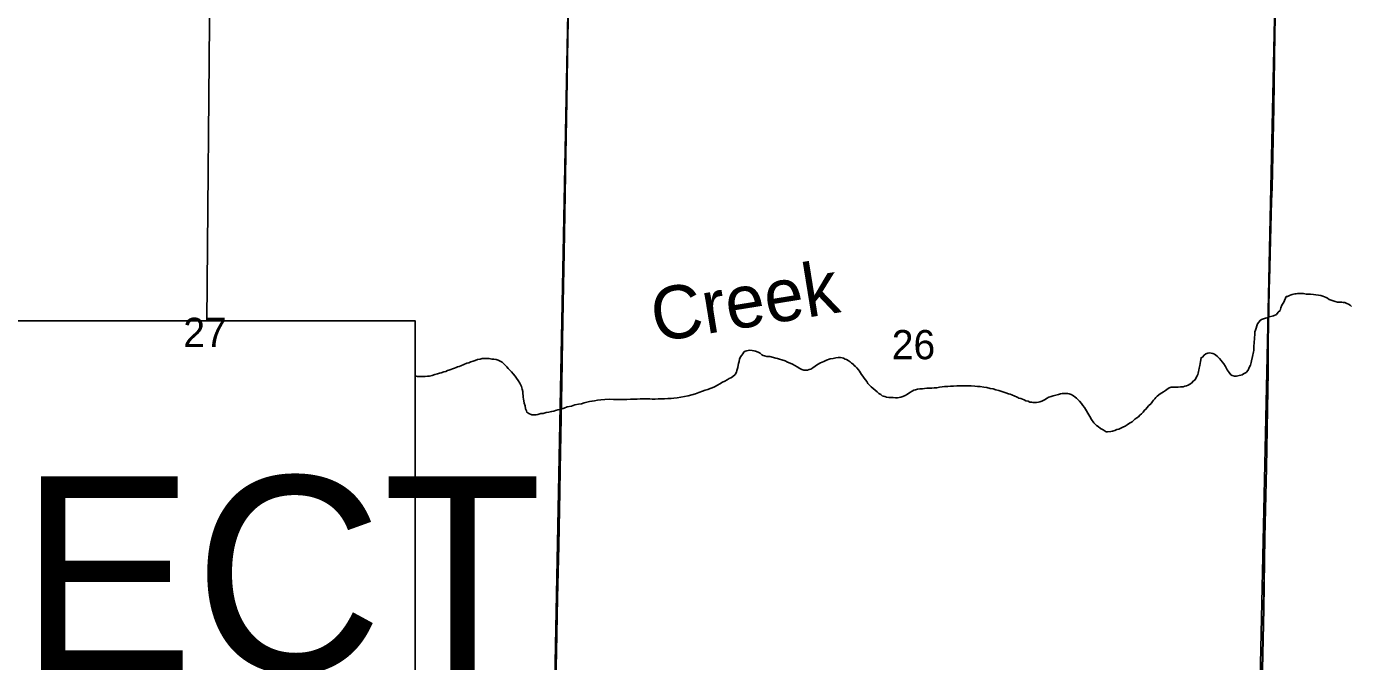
# Model space of a CAD drawing. Extents: x 2.4 to 73.1, y 4.5 to 25.6.
# Drawn here: x 32.094 to 33.042, y 19.109 to 19.564 of the extents above; entities that cross this region are included whole.
import ezdxf

# ---------------------------------------------------------------- set-up
doc = ezdxf.new("R2010")
doc.units = 0
for name, color, linetype in [('GM_X_Minor_Lake_Text', 7, 'Continuous'), ('GM_X_Minor_River', 7, 'Continuous'), ('GM_X_Section', 7, 'Continuous'), ('GM_X_Section_Text', 7, 'Continuous'), ('GM_X_State_Route', 7, 'Continuous'), ('GM_X_Township', 7, 'Continuous'), ('GM_X_Township_Road', 7, 'Continuous'), ('SH_Text', 7, 'Continuous')]:
    doc.layers.add(name, color=color, linetype=linetype)

msp = doc.modelspace()

# ---------------------------------------------------------------- linework, layer by layer
at = {"layer": 'GM_X_Minor_River'}
for points in [[(32.22285, 19.35283), (32.22507, 19.59303), (30.44608, 19.62066)], [(33.04282, 19.36291), (33.04187, 19.36386), (33.04073, 19.36463), (33.03959, 19.3652), (33.03807, 19.36578), (33.03693, 19.36597), (33.03579, 19.36616), (33.03465, 19.36617), (33.0337, 19.36617), (33.03275, 19.36617), (33.03104, 19.36656), (33.02971, 19.36694), (33.02838, 19.36751), (33.02686, 19.36809), (33.02553, 19.36885), (33.02458, 19.36943), (33.02344, 19.37), (33.0223, 19.37038), (33.02078, 19.37096), (33.01565, 19.37154), (33.01356, 19.37174), (33.01204, 19.37193), (33.01033, 19.37194), (33.00842, 19.37232), (33.00691, 19.37233), (33.00576, 19.37233), (33.00424, 19.37234), (33.00329, 19.37215), (33.00234, 19.37215), (33.00044, 19.37159), (32.99949, 19.3714), (32.99853, 19.37083), (32.99701, 19.37027), (32.99606, 19.37008), (32.99434, 19.36609), (32.99301, 19.364), (32.99224, 19.36192), (32.99167, 19.36021), (32.99033, 19.35888), (32.989, 19.35717), (32.98691, 19.35642), (32.98596, 19.35604), (32.98386, 19.35548), (32.98253, 19.35491), (32.9812, 19.35454), (32.97968, 19.35416), (32.97835, 19.35359)], [(32.97835, 19.35359), (32.97739, 19.35303), (32.97644, 19.35189), (32.97549, 19.35056), (32.97396, 19.34601), (32.97357, 19.34487), (32.97357, 19.34316), (32.97337, 19.34031), (32.97318, 19.33708), (32.97298, 19.33461), (32.97279, 19.33157), (32.97259, 19.33043), (32.97202, 19.3272), (32.97125, 19.32416), (32.97087, 19.32283), (32.97048, 19.32093), (32.96953, 19.31922), (32.96876, 19.31752), (32.96743, 19.31581), (32.96648, 19.31524), (32.96553, 19.31467), (32.96457, 19.31411), (32.96362, 19.31392), (32.96229, 19.31354), (32.96039, 19.31317), (32.95906, 19.31317), (32.95735, 19.31356), (32.9564, 19.31413), (32.95526, 19.31565), (32.95374, 19.31775), (32.95261, 19.32003), (32.95128, 19.32194), (32.95014, 19.32346), (32.94938, 19.32441), (32.94825, 19.32575), (32.94692, 19.32727), (32.94559, 19.32803), (32.94464, 19.3288), (32.9435, 19.32937), (32.94236, 19.32956), (32.94141, 19.32976), (32.93989, 19.32957), (32.93837, 19.3292), (32.93722, 19.32825), (32.93608, 19.32673), (32.93513, 19.32635), (32.93474, 19.3235), (32.93416, 19.32084), (32.93359, 19.31876), (32.9334, 19.31743), (32.93321, 19.31648), (32.93301, 19.31534), (32.93263, 19.3142), (32.93225, 19.31325), (32.93148, 19.31211), (32.93072, 19.31059), (32.92958, 19.30965), (32.92824, 19.30813), (32.9271, 19.30737), (32.92577, 19.30662), (32.92463, 19.30624), (32.92349, 19.30586), (32.92215, 19.30549), (32.92025, 19.30549), (32.91854, 19.30531), (32.91702, 19.30531), (32.91607, 19.30531), (32.91474, 19.30532), (32.9136, 19.30532), (32.91227, 19.30475), (32.91055, 19.30362), (32.9096, 19.30286), (32.90808, 19.30192), (32.90693, 19.30116), (32.90579, 19.3004), (32.90351, 19.2987), (32.90274, 19.29775), (32.90198, 19.2968), (32.90103, 19.29586), (32.90027, 19.29491), (32.89931, 19.29358), (32.89741, 19.29187), (32.89646, 19.29055), (32.8955, 19.28941), (32.89455, 19.28865), (32.8936, 19.28732), (32.89245, 19.28619), (32.89131, 19.28524), (32.89017, 19.2841), (32.88902, 19.28316), (32.88769, 19.28221), (32.88655, 19.28145), (32.8856, 19.28032), (32.88369, 19.27937), (32.88217, 19.27824), (32.88065, 19.27729), (32.87893, 19.27653), (32.8776, 19.27578), (32.87627, 19.27521), (32.87475, 19.27484), (32.87322, 19.27408)], [(32.71146, 19.29792), (32.70975, 19.29811), (32.70842, 19.2985), (32.70747, 19.29869), (32.70652, 19.29907), (32.70557, 19.30002), (32.70424, 19.30079), (32.70292, 19.30193), (32.69874, 19.30556), (32.6976, 19.3067), (32.69646, 19.30784), (32.69551, 19.30917), (32.69457, 19.31051), (32.69362, 19.31165), (32.69267, 19.31317), (32.69191, 19.31432), (32.69115, 19.31546), (32.6904, 19.31679), (32.68964, 19.31774), (32.6885, 19.31908), (32.68755, 19.32003), (32.6866, 19.32079), (32.68584, 19.32175), (32.68471, 19.32251), (32.68357, 19.32346), (32.68224, 19.32442), (32.6811, 19.32499), (32.68015, 19.32537), (32.67901, 19.32595), (32.67806, 19.32614), (32.67673, 19.32652), (32.67502, 19.32653), (32.67349, 19.32634), (32.67159, 19.32578), (32.66931, 19.3254), (32.66684, 19.32465), (32.66474, 19.32371), (32.66246, 19.32257), (32.66036, 19.32144), (32.65865, 19.3203), (32.65694, 19.31898), (32.65541, 19.31822), (32.65427, 19.31784), (32.65313, 19.31747), (32.6518, 19.31747), (32.65047, 19.31748), (32.64914, 19.31786), (32.64762, 19.31862), (32.64572, 19.31977), (32.64401, 19.32072), (32.6423, 19.32168), (32.64059, 19.32244), (32.63888, 19.32321), (32.63717, 19.32397), (32.6347, 19.32474), (32.63318, 19.32532), (32.63166, 19.3257), (32.63033, 19.32608), (32.62615, 19.32724), (32.62501, 19.32724), (32.62387, 19.32724), (32.62235, 19.32763), (32.6214, 19.32782), (32.62045, 19.32839), (32.61931, 19.32954), (32.61779, 19.3303), (32.61589, 19.33107), (32.61475, 19.33126), (32.61342, 19.33145), (32.6119, 19.33165), (32.61057, 19.33146), (32.60962, 19.33127), (32.60848, 19.3309), (32.60752, 19.33033), (32.60676, 19.32919), (32.606, 19.32805), (32.60524, 19.32692), (32.60447, 19.32521), (32.60409, 19.32369), (32.60371, 19.32217), (32.60351, 19.32103), (32.60313, 19.31932), (32.60255, 19.31723), (32.60217, 19.3159), (32.60122, 19.31438), (32.59931, 19.31268), (32.59817, 19.31192), (32.59703, 19.31136), (32.5955, 19.31041), (32.59379, 19.30946), (32.59227, 19.30871), (32.59036, 19.30757), (32.58865, 19.30663), (32.58656, 19.30549), (32.58484, 19.30474), (32.58351, 19.30417), (32.58161, 19.30361), (32.57971, 19.30304), (32.5778, 19.30229), (32.57533, 19.30135), (32.57286, 19.3004)], [(32.57286, 19.3004), (32.57019, 19.29965), (32.56772, 19.29909), (32.55973, 19.29759), (32.55745, 19.29741), (32.55536, 19.29703), (32.55307, 19.29704), (32.55079, 19.29685), (32.54851, 19.29686), (32.54623, 19.29687), (32.54395, 19.29668), (32.54186, 19.29669), (32.54014, 19.29688), (32.53824, 19.29689), (32.53539, 19.2969), (32.5333, 19.2969), (32.53102, 19.29672), (32.52874, 19.29654), (32.52626, 19.29654), (32.52379, 19.29636), (32.52151, 19.29637), (32.51904, 19.29637), (32.51676, 19.29638), (32.51409, 19.29639), (32.51143, 19.29659), (32.50782, 19.29641), (32.50516, 19.29622), (32.50269, 19.29585), (32.50059, 19.29548), (32.49869, 19.2951), (32.49698, 19.29492), (32.49508, 19.29454), (32.49317, 19.29398), (32.49127, 19.29341), (32.48899, 19.29304), (32.48652, 19.29248), (32.48404, 19.29172), (32.481, 19.29116), (32.47872, 19.29022), (32.47643, 19.28946), (32.47434, 19.2889), (32.47263, 19.28853), (32.4713, 19.28815), (32.46977, 19.28777), (32.46787, 19.2874), (32.46597, 19.28702), (32.46369, 19.28646), (32.46216, 19.28627), (32.45988, 19.28571), (32.45855, 19.28533), (32.4576, 19.28534), (32.45665, 19.28534), (32.4557, 19.28553), (32.45342, 19.2863), (32.45209, 19.28725), (32.45171, 19.28839), (32.45114, 19.28973), (32.45077, 19.29182), (32.4502, 19.29372), (32.44983, 19.29543), (32.44964, 19.29657), (32.44945, 19.29809), (32.44945, 19.29923), (32.44927, 19.30056), (32.44908, 19.30208), (32.4487, 19.3038), (32.44833, 19.3057), (32.447, 19.30817), (32.44586, 19.31007), (32.44473, 19.3116), (32.44359, 19.31312), (32.44226, 19.31484), (32.44112, 19.31617), (32.43979, 19.3175), (32.43866, 19.31865), (32.43771, 19.31979), (32.43676, 19.32074), (32.43562, 19.32189), (32.43429, 19.32303), (32.43296, 19.32379), (32.43163, 19.32456), (32.43011, 19.32494), (32.42821, 19.32533), (32.42688, 19.32533), (32.42498, 19.32572), (32.42327, 19.32572), (32.42175, 19.32573), (32.42004, 19.32573), (32.41851, 19.32536), (32.4168, 19.32498), (32.41509, 19.32441), (32.41357, 19.32385), (32.41205, 19.32328), (32.41052, 19.32272), (32.40919, 19.32234), (32.40481, 19.32045), (32.40348, 19.32008), (32.40234, 19.3197), (32.40139, 19.31932), (32.40025, 19.31895), (32.39892, 19.31838)], [(32.39892, 19.31838), (32.39758, 19.31781), (32.39625, 19.31744), (32.39511, 19.31706), (32.39397, 19.31649), (32.39264, 19.31631), (32.39073, 19.31555), (32.38959, 19.31518), (32.38807, 19.3148), (32.38617, 19.31424), (32.38426, 19.31348), (32.38236, 19.31311), (32.38084, 19.31311), (32.37932, 19.31292), (32.37761, 19.31293), (32.3759, 19.31293), (32.37362, 19.31294), (32.3721, 19.31332), (32.37206, 19.31333)], [(32.87322, 19.27408), (32.8717, 19.2737), (32.87037, 19.27352), (32.86809, 19.27315), (32.86714, 19.27315), (32.86486, 19.27467), (32.86296, 19.27563), (32.86125, 19.27697), (32.86011, 19.27773), (32.85916, 19.27868), (32.85821, 19.27963), (32.85651, 19.28211), (32.85537, 19.2842), (32.85158, 19.29068), (32.85044, 19.2922), (32.8495, 19.29353), (32.84798, 19.29525), (32.84684, 19.29639), (32.84589, 19.29734), (32.84494, 19.29811), (32.84361, 19.29906), (32.84209, 19.30002), (32.84057, 19.3004), (32.83962, 19.30059), (32.83867, 19.30078), (32.83772, 19.30079), (32.83658, 19.30079), (32.83563, 19.30079), (32.8343, 19.30042), (32.83297, 19.30004), (32.83107, 19.29948), (32.82916, 19.29891), (32.82764, 19.29854), (32.82612, 19.29797), (32.82441, 19.29702), (32.82345, 19.29646), (32.82231, 19.29589), (32.82098, 19.29513), (32.81965, 19.29476), (32.81851, 19.29438), (32.81717, 19.29419), (32.81603, 19.2942), (32.8147, 19.2942), (32.81375, 19.29439), (32.81242, 19.29459), (32.81109, 19.29516), (32.80957, 19.29555), (32.80824, 19.29612), (32.8071, 19.29669), (32.80596, 19.29708), (32.80463, 19.29746), (32.80368, 19.29784), (32.80273, 19.29842), (32.80159, 19.2988), (32.7995, 19.29976), (32.79836, 19.30014), (32.79703, 19.30052), (32.79532, 19.3011), (32.79019, 19.30282), (32.7881, 19.3034), (32.78601, 19.30398), (32.78392, 19.30436), (32.78164, 19.30494), (32.77936, 19.30532), (32.7767, 19.30571), (32.7748, 19.30572), (32.7729, 19.30591), (32.77042, 19.30611), (32.76814, 19.30612), (32.76548, 19.30612), (32.76282, 19.30613), (32.76016, 19.30614), (32.75768, 19.30596), (32.75559, 19.30596), (32.75369, 19.30578), (32.75122, 19.3056), (32.7497, 19.30541), (32.7478, 19.30523), (32.7457, 19.30485), (32.7438, 19.30467), (32.74209, 19.30448), (32.74038, 19.30449), (32.73867, 19.30449), (32.73696, 19.30431), (32.73543, 19.30412), (32.73353, 19.30394), (32.73201, 19.30375), (32.73049, 19.30337), (32.72935, 19.303), (32.72801, 19.30243), (32.72649, 19.3013), (32.72478, 19.30016), (32.72307, 19.29921), (32.72135, 19.29846), (32.72002, 19.29808), (32.71888, 19.2979), (32.71755, 19.29771), (32.71622, 19.29771), (32.71451, 19.29772), (32.71298, 19.29791), (32.71146, 19.29792)]]:
    msp.add_lwpolyline(points, dxfattribs=at)
at = {"layer": 'GM_X_Section'}
for points in [[(32.37206, 19.09708), (32.47209, 19.0957), (32.48193, 19.59785), (31.97137, 19.60585), (31.96815, 19.35283), (32.37206, 19.35283)], [(32.98811, 19.59151), (32.97722, 19.08485), (32.47209, 19.0957), (32.48193, 19.59785)], [(33.49557, 19.58326), (33.48089, 19.0765), (32.97722, 19.08485), (32.98811, 19.59151)]]:
    msp.add_lwpolyline(points, close=True, dxfattribs=at)
at = {"layer": 'GM_X_State_Route'}
msp.add_lwpolyline([(32.97862, 19.08536), (32.9788, 19.09205), (32.98002, 19.14643), (32.98085, 19.19771), (32.98195, 19.24744), (32.98296, 19.30338), (32.98311, 19.31581), (32.98323, 19.33756), (32.98394, 19.37486), (32.98428, 19.3904), (32.98452, 19.40127), (32.98504, 19.41991), (32.98561, 19.43854), (32.98595, 19.44786), (32.98649, 19.47116), (32.98718, 19.50534), (32.98801, 19.55818), (32.98866, 19.59177)], dxfattribs=at)
at = {"layer": 'GM_X_Township'}
msp.add_lwpolyline([(32.98854, 19.59204), (32.9879, 19.55846), (32.98706, 19.50562), (32.98637, 19.47143), (32.98583, 19.44813), (32.9855, 19.43882), (32.98493, 19.42019), (32.9844, 19.40154), (32.98417, 19.39067), (32.98382, 19.37514), (32.98312, 19.33784), (32.98299, 19.31609), (32.98284, 19.30366), (32.98184, 19.24771), (32.98074, 19.19799), (32.9799, 19.14671), (32.97868, 19.09233)], dxfattribs=at)
at = {"layer": 'GM_X_Township_Road'}
msp.add_lwpolyline([(32.47285, 19.09527), (32.47336, 19.11545), (32.47399, 19.1543), (32.47487, 19.19158), (32.47567, 19.23043), (32.47595, 19.24597), (32.47702, 19.30812), (32.47752, 19.3392), (32.47821, 19.37805), (32.47871, 19.40136), (32.47919, 19.42933), (32.47995, 19.47128), (32.48061, 19.51013), (32.48118, 19.54121), (32.48198, 19.58161), (32.48216, 19.59559), (32.48221, 19.59784)], dxfattribs=at)
at = {"layer": 'SH_Text'}
msp.add_lwpolyline([(30.86803, 18.77027), (32.37206, 18.77027), (32.37206, 19.35283), (30.86803, 19.35283)], close=True, dxfattribs=at)

# ---------------------------------------------------------------- texts
at = {"layer": 'GM_X_Minor_Lake_Text'}
msp.add_text('Creek', height=0.037899, rotation=9.19992, dxfattribs=at).set_placement((32.54427, 19.3374))
at = {"layer": 'GM_X_Section_Text'}
for s, p in [('27', (32.20597, 19.33398)), ('26', (32.71347, 19.32523))]:
    msp.add_text(s, height=0.020928, rotation=0.00001, dxfattribs=at).set_placement(p)
at = {"layer": 'SH_Text'}
msp.add_text('BEGIN PROJECT', height=0.1399997, rotation=360, dxfattribs=at).set_placement((30.95487, 19.10137))

doc.saveas('drawing.dxf')
